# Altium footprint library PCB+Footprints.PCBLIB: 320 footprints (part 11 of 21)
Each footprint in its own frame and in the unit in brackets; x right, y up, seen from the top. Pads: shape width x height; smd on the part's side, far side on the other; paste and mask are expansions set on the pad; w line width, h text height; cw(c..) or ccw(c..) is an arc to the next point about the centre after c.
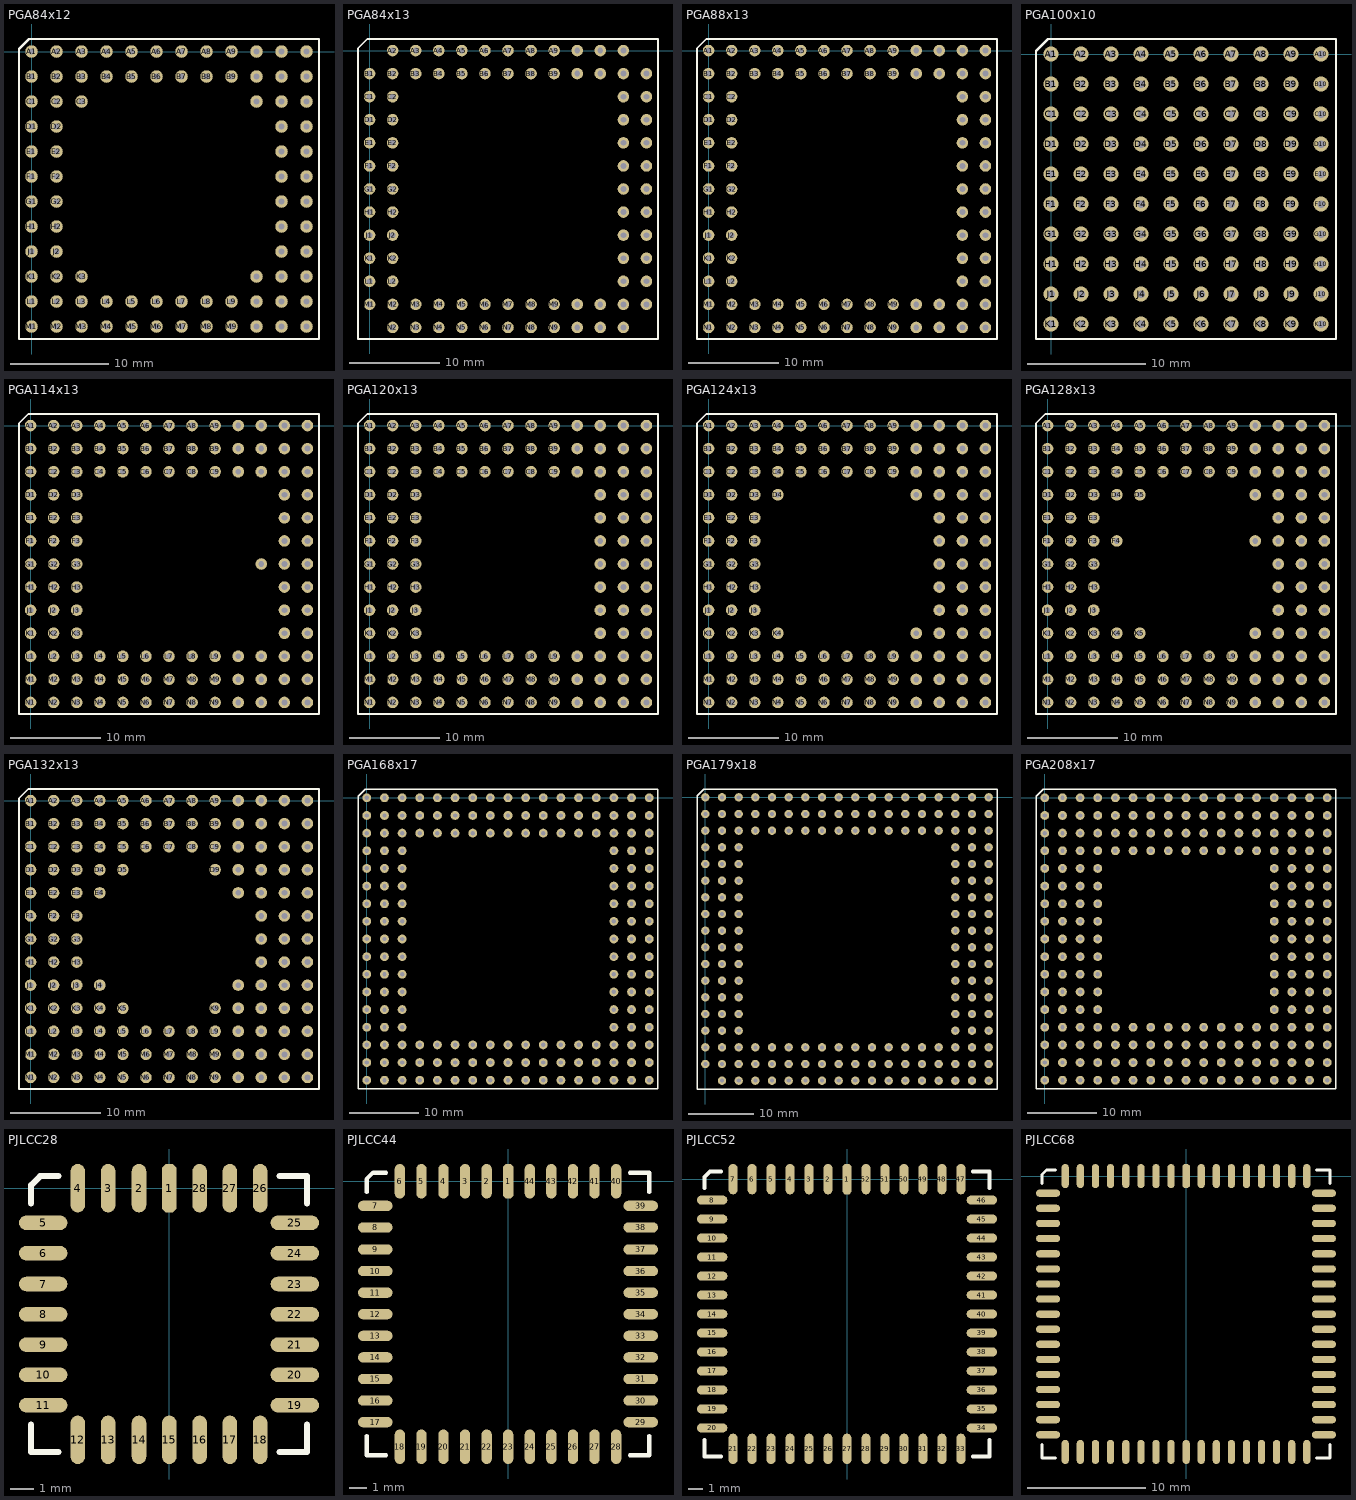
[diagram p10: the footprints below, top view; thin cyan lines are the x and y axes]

## PGA84x12 [mil]
pads (84):
  round 50 hole 25: A1(0,0) A2(100,0) A3(200,0) A4(300,0) A5(400,0) A6(500,0) A7(600,0) A8(700,0) A9(800,0) A10(900,0) A11(1000,0) A12(1100,0) B1(0,-100) B2(100,-100) B3(200,-100) B4(300,-100) B5(400,-100) B6(500,-100) B7(600,-100) B8(700,-100) B9(800,-100) B10(900,-100) B11(1000,-100) B12(1100,-100) C1(0,-200) C2(100,-200) C3(200,-200) C10(900,-200) C11(1000,-200) C12(1100,-200) D1(0,-300) D2(100,-300) D11(1000,-300) D12(1100,-300) E1(0,-400) E2(100,-400) E11(1000,-400) E12(1100,-400) F1(0,-500) F2(100,-500) F11(1000,-500) F12(1100,-500) G1(0,-600) G2(100,-600) G11(1000,-600) G12(1100,-600) H1(0,-700) H2(100,-700) H11(1000,-700) H12(1100,-700) J1(0,-800) J2(100,-800) J11(1000,-800) J12(1100,-800) K1(0,-900) K2(100,-900) K3(200,-900) K10(900,-900) K11(1000,-900) K12(1100,-900) L1(0,-1000) L2(100,-1000) L3(200,-1000) L4(300,-1000) L5(400,-1000) L6(500,-1000) L7(600,-1000) L8(700,-1000) L9(800,-1000) L10(900,-1000) L11(1000,-1000) L12(1100,-1000) M1(0,-1100) M2(100,-1100) M3(200,-1100) M4(300,-1100) M5(400,-1100) M6(500,-1100) M7(600,-1100) M8(700,-1100) M9(800,-1100) M10(900,-1100) M11(1000,-1100) M12(1100,-1100)
TopOverlay:
  lines w8: -50,-1150 1150,-1150 1150,50 -10,50 -50,10 -50,-1150

## PGA84x13 [mil]
pads (84):
  round 50 hole 25: A2(100,0) A3(200,0) A4(300,0) A5(400,0) A6(500,0) A7(600,0) A8(700,0) A9(800,0) A10(900,0) A11(1000,0) A12(1100,0) B1(0,-100) B2(100,-100) B3(200,-100) B4(300,-100) B5(400,-100) B6(500,-100) B7(600,-100) B8(700,-100) B9(800,-100) B10(900,-100) B11(1000,-100) B12(1100,-100) B13(1200,-100) C1(0,-200) C2(100,-200) C12(1100,-200) C13(1200,-200) D1(0,-300) D2(100,-300) D12(1100,-300) D13(1200,-300) E1(0,-400) E2(100,-400) E12(1100,-400) E13(1200,-400) F1(0,-500) F2(100,-500) F12(1100,-500) F13(1200,-500) G1(0,-600) G2(100,-600) G12(1100,-600) G13(1200,-600) H1(0,-700) H2(100,-700) H12(1100,-700) H13(1200,-700) J1(0,-800) J2(100,-800) J12(1100,-800) J13(1200,-800) K1(0,-900) K2(100,-900) K12(1100,-900) K13(1200,-900) L1(0,-1000) L2(100,-1000) L12(1100,-1000) L13(1200,-1000) M1(0,-1100) M2(100,-1100) M3(200,-1100) M4(300,-1100) M5(400,-1100) M6(500,-1100) M7(600,-1100) M8(700,-1100) M9(800,-1100) M10(900,-1100) M11(1000,-1100) M12(1100,-1100) M13(1200,-1100) N2(100,-1200) N3(200,-1200) N4(300,-1200) N5(400,-1200) N6(500,-1200) N7(600,-1200) N8(700,-1200) N9(800,-1200) N10(900,-1200) N11(1000,-1200) N12(1100,-1200)
TopOverlay:
  lines w8: -50,-1250 1250,-1250 1250,50 -10,50 -50,10 -50,-1250

## PGA88x13 [mil]
pads (88):
  round 50 hole 25: A1(0,0) A2(100,0) A3(200,0) A4(300,0) A5(400,0) A6(500,0) A7(600,0) A8(700,0) A9(800,0) A10(900,0) A11(1000,0) A12(1100,0) A13(1200,0) B1(0,-100) B2(100,-100) B3(200,-100) B4(300,-100) B5(400,-100) B6(500,-100) B7(600,-100) B8(700,-100) B9(800,-100) B10(900,-100) B11(1000,-100) B12(1100,-100) B13(1200,-100) C1(0,-200) C2(100,-200) C12(1100,-200) C13(1200,-200) D1(0,-300) D2(100,-300) D12(1100,-300) D13(1200,-300) E1(0,-400) E2(100,-400) E12(1100,-400) E13(1200,-400) F1(0,-500) F2(100,-500) F12(1100,-500) F13(1200,-500) G1(0,-600) G2(100,-600) G12(1100,-600) G13(1200,-600) H1(0,-700) H2(100,-700) H12(1100,-700) H13(1200,-700) J1(0,-800) J2(100,-800) J12(1100,-800) J13(1200,-800) K1(0,-900) K2(100,-900) K12(1100,-900) K13(1200,-900) L1(0,-1000) L2(100,-1000) L12(1100,-1000) L13(1200,-1000) M1(0,-1100) M2(100,-1100) M3(200,-1100) M4(300,-1100) M5(400,-1100) M6(500,-1100) M7(600,-1100) M8(700,-1100) M9(800,-1100) M10(900,-1100) M11(1000,-1100) M12(1100,-1100) M13(1200,-1100) N1(0,-1200) N2(100,-1200) N3(200,-1200) N4(300,-1200) N5(400,-1200) N6(500,-1200) N7(600,-1200) N8(700,-1200) N9(800,-1200) N10(900,-1200) N11(1000,-1200) N12(1100,-1200) N13(1200,-1200)
TopOverlay:
  lines w8: -50,-1250 1250,-1250 1250,50 -10,50 -50,10 -50,-1250

## PGA100x10 [mil]
pads (100):
  round 50 hole 25: A1(0,0) A2(100,0) A3(200,0) A4(300,0) A5(400,0) A6(500,0) A7(600,0) A8(700,0) A9(800,0) A10(900,0) B1(0,-100) B2(100,-100) B3(200,-100) B4(300,-100) B5(400,-100) B6(500,-100) B7(600,-100) B8(700,-100) B9(800,-100) B10(900,-100) C1(0,-200) C2(100,-200) C3(200,-200) C4(300,-200) C5(400,-200) C6(500,-200) C7(600,-200) C8(700,-200) C9(800,-200) C10(900,-200) D1(0,-300) D2(100,-300) D3(200,-300) D4(300,-300) D5(400,-300) D6(500,-300) D7(600,-300) D8(700,-300) D9(800,-300) D10(900,-300) E1(0,-400) E2(100,-400) E3(200,-400) E4(300,-400) E5(400,-400) E6(500,-400) E7(600,-400) E8(700,-400) E9(800,-400) E10(900,-400) F1(0,-500) F2(100,-500) F3(200,-500) F4(300,-500) F5(400,-500) F6(500,-500) F7(600,-500) F8(700,-500) F9(800,-500) F10(900,-500) G1(0,-600) G2(100,-600) G3(200,-600) G4(300,-600) G5(400,-600) G6(500,-600) G7(600,-600) G8(700,-600) G9(800,-600) G10(900,-600) H1(0,-700) H2(100,-700) H3(200,-700) H4(300,-700) H5(400,-700) H6(500,-700) H7(600,-700) H8(700,-700) H9(800,-700) H10(900,-700) J1(0,-800) J2(100,-800) J3(200,-800) J4(300,-800) J5(400,-800) J6(500,-800) J7(600,-800) J8(700,-800) J9(800,-800) J10(900,-800) K1(0,-900) K2(100,-900) K3(200,-900) K4(300,-900) K5(400,-900) K6(500,-900) K7(600,-900) K8(700,-900) K9(800,-900) K10(900,-900)
TopOverlay:
  lines w8: -50,-950 950,-950 950,50 -10,50 -50,10 -50,-950

## PGA114x13 [mil]
pads (114):
  round 50 hole 25: A1(0,0) A2(100,0) A3(200,0) A4(300,0) A5(400,0) A6(500,0) A7(600,0) A8(700,0) A9(800,0) A10(900,0) A11(1000,0) A12(1100,0) A13(1200,0) B1(0,-100) B2(100,-100) B3(200,-100) B4(300,-100) B5(400,-100) B6(500,-100) B7(600,-100) B8(700,-100) B9(800,-100) B10(900,-100) B11(1000,-100) B12(1100,-100) B13(1200,-100) C1(0,-200) C2(100,-200) C3(200,-200) C4(300,-200) C5(400,-200) C6(500,-200) C7(600,-200) C8(700,-200) C9(800,-200) C10(900,-200) C11(1000,-200) C12(1100,-200) C13(1200,-200) D1(0,-300) D2(100,-300) D3(200,-300) D12(1100,-300) D13(1200,-300) E1(0,-400) E2(100,-400) E3(200,-400) E12(1100,-400) E13(1200,-400) F1(0,-500) F2(100,-500) F3(200,-500) F12(1100,-500) F13(1200,-500) G1(0,-600) G2(100,-600) G3(200,-600) G11(1000,-600) G12(1100,-600) G13(1200,-600) H1(0,-700) H2(100,-700) H3(200,-700) H12(1100,-700) H13(1200,-700) J1(0,-800) J2(100,-800) J3(200,-800) J12(1100,-800) J13(1200,-800) K1(0,-900) K2(100,-900) K3(200,-900) K12(1100,-900) K13(1200,-900) L1(0,-1000) L2(100,-1000) L3(200,-1000) L4(300,-1000) L5(400,-1000) L6(500,-1000) L7(600,-1000) L8(700,-1000) L9(800,-1000) L10(900,-1000) L11(1000,-1000) L12(1100,-1000) L13(1200,-1000) M1(0,-1100) M2(100,-1100) M3(200,-1100) M4(300,-1100) M5(400,-1100) M6(500,-1100) M7(600,-1100) M8(700,-1100) M9(800,-1100) M10(900,-1100) M11(1000,-1100) M12(1100,-1100) M13(1200,-1100) N1(0,-1200) N2(100,-1200) N3(200,-1200) N4(300,-1200) N5(400,-1200) N6(500,-1200) N7(600,-1200) N8(700,-1200) N9(800,-1200) N10(900,-1200) N11(1000,-1200) N12(1100,-1200) N13(1200,-1200)
TopOverlay:
  lines w8: -50,-1250 1250,-1250 1250,50 -10,50 -50,10 -50,-1250

## PGA120x13 [mil]
pads (120):
  round 50 hole 25: A1(0,0) A2(100,0) A3(200,0) A4(300,0) A5(400,0) A6(500,0) A7(600,0) A8(700,0) A9(800,0) A10(900,0) A11(1000,0) A12(1100,0) A13(1200,0) B1(0,-100) B2(100,-100) B3(200,-100) B4(300,-100) B5(400,-100) B6(500,-100) B7(600,-100) B8(700,-100) B9(800,-100) B10(900,-100) B11(1000,-100) B12(1100,-100) B13(1200,-100) C1(0,-200) C2(100,-200) C3(200,-200) C4(300,-200) C5(400,-200) C6(500,-200) C7(600,-200) C8(700,-200) C9(800,-200) C10(900,-200) C11(1000,-200) C12(1100,-200) C13(1200,-200) D1(0,-300) D2(100,-300) D3(200,-300) D11(1000,-300) D12(1100,-300) D13(1200,-300) E1(0,-400) E2(100,-400) E3(200,-400) E11(1000,-400) E12(1100,-400) E13(1200,-400) F1(0,-500) F2(100,-500) F3(200,-500) F11(1000,-500) F12(1100,-500) F13(1200,-500) G1(0,-600) G2(100,-600) G3(200,-600) G11(1000,-600) G12(1100,-600) G13(1200,-600) H1(0,-700) H2(100,-700) H3(200,-700) H11(1000,-700) H12(1100,-700) H13(1200,-700) J1(0,-800) J2(100,-800) J3(200,-800) J11(1000,-800) J12(1100,-800) J13(1200,-800) K1(0,-900) K2(100,-900) K3(200,-900) K11(1000,-900) K12(1100,-900) K13(1200,-900) L1(0,-1000) L2(100,-1000) L3(200,-1000) L4(300,-1000) L5(400,-1000) L6(500,-1000) L7(600,-1000) L8(700,-1000) L9(800,-1000) L10(900,-1000) L11(1000,-1000) L12(1100,-1000) L13(1200,-1000) M1(0,-1100) M2(100,-1100) M3(200,-1100) M4(300,-1100) M5(400,-1100) M6(500,-1100) M7(600,-1100) M8(700,-1100) M9(800,-1100) M10(900,-1100) M11(1000,-1100) M12(1100,-1100) M13(1200,-1100) N1(0,-1200) N2(100,-1200) N3(200,-1200) N4(300,-1200) N5(400,-1200) N6(500,-1200) N7(600,-1200) N8(700,-1200) N9(800,-1200) N10(900,-1200) N11(1000,-1200) N12(1100,-1200) N13(1200,-1200)
TopOverlay:
  lines w8: -50,-1250 -50,10 -10,50 1250,50 1250,-1250 -50,-1250

## PGA124x13 [mil]
pads (124):
  round 50 hole 25: A1(0,0) A2(100,0) A3(200,0) A4(300,0) A5(400,0) A6(500,0) A7(600,0) A8(700,0) A9(800,0) A10(900,0) A11(1000,0) A12(1100,0) A13(1200,0) B1(0,-100) B2(100,-100) B3(200,-100) B4(300,-100) B5(400,-100) B6(500,-100) B7(600,-100) B8(700,-100) B9(800,-100) B10(900,-100) B11(1000,-100) B12(1100,-100) B13(1200,-100) C1(0,-200) C2(100,-200) C3(200,-200) C4(300,-200) C5(400,-200) C6(500,-200) C7(600,-200) C8(700,-200) C9(800,-200) C10(900,-200) C11(1000,-200) C12(1100,-200) C13(1200,-200) D1(0,-300) D2(100,-300) D3(200,-300) D4(300,-300) D10(900,-300) D11(1000,-300) D12(1100,-300) D13(1200,-300) E1(0,-400) E2(100,-400) E3(200,-400) E11(1000,-400) E12(1100,-400) E13(1200,-400) F1(0,-500) F2(100,-500) F3(200,-500) F11(1000,-500) F12(1100,-500) F13(1200,-500) G1(0,-600) G2(100,-600) G3(200,-600) G11(1000,-600) G12(1100,-600) G13(1200,-600) H1(0,-700) H2(100,-700) H3(200,-700) H11(1000,-700) H12(1100,-700) H13(1200,-700) J1(0,-800) J2(100,-800) J3(200,-800) J11(1000,-800) J12(1100,-800) J13(1200,-800) K1(0,-900) K2(100,-900) K3(200,-900) K4(300,-900) K10(900,-900) K11(1000,-900) K12(1100,-900) K13(1200,-900) L1(0,-1000) L2(100,-1000) L3(200,-1000) L4(300,-1000) L5(400,-1000) L6(500,-1000) L7(600,-1000) L8(700,-1000) L9(800,-1000) L10(900,-1000) L11(1000,-1000) L12(1100,-1000) L13(1200,-1000) M1(0,-1100) M2(100,-1100) M3(200,-1100) M4(300,-1100) M5(400,-1100) M6(500,-1100) M7(600,-1100) M8(700,-1100) M9(800,-1100) M10(900,-1100) M11(1000,-1100) M12(1100,-1100) M13(1200,-1100) N1(0,-1200) N2(100,-1200) N3(200,-1200) N4(300,-1200) N5(400,-1200) N6(500,-1200) N7(600,-1200) N8(700,-1200) N9(800,-1200) N10(900,-1200) N11(1000,-1200) N12(1100,-1200) N13(1200,-1200)
TopOverlay:
  lines w8: -50,-1250 -50,10 -10,50 1250,50 1250,-1250 -50,-1250

## PGA128x13 [mil]
pads (128):
  round 50 hole 25: A1(0,0) A2(100,0) A3(200,0) A4(300,0) A5(400,0) A6(500,0) A7(600,0) A8(700,0) A9(800,0) A10(900,0) A11(1000,0) A12(1100,0) A13(1200,0) B1(0,-100) B2(100,-100) B3(200,-100) B4(300,-100) B5(400,-100) B6(500,-100) B7(600,-100) B8(700,-100) B9(800,-100) B10(900,-100) B11(1000,-100) B12(1100,-100) B13(1200,-100) C1(0,-200) C2(100,-200) C3(200,-200) C4(300,-200) C5(400,-200) C6(500,-200) C7(600,-200) C8(700,-200) C9(800,-200) C10(900,-200) C11(1000,-200) C12(1100,-200) C13(1200,-200) D1(0,-300) D2(100,-300) D3(200,-300) D4(300,-300) D5(400,-300) D10(900,-300) D11(1000,-300) D12(1100,-300) D13(1200,-300) E1(0,-400) E2(100,-400) E3(200,-400) E11(1000,-400) E12(1100,-400) E13(1200,-400) F1(0,-500) F2(100,-500) F3(200,-500) F4(300,-500) F10(900,-500) F11(1000,-500) F12(1100,-500) F13(1200,-500) G1(0,-600) G2(100,-600) G3(200,-600) G11(1000,-600) G12(1100,-600) G13(1200,-600) H1(0,-700) H2(100,-700) H3(200,-700) H11(1000,-700) H12(1100,-700) H13(1200,-700) J1(0,-800) J2(100,-800) J3(200,-800) J11(1000,-800) J12(1100,-800) J13(1200,-800) K1(0,-900) K2(100,-900) K3(200,-900) K4(300,-900) K5(400,-900) K10(900,-900) K11(1000,-900) K12(1100,-900) K13(1200,-900) L1(0,-1000) L2(100,-1000) L3(200,-1000) L4(300,-1000) L5(400,-1000) L6(500,-1000) L7(600,-1000) L8(700,-1000) L9(800,-1000) L10(900,-1000) L11(1000,-1000) L12(1100,-1000) L13(1200,-1000) M1(0,-1100) M2(100,-1100) M3(200,-1100) M4(300,-1100) M5(400,-1100) M6(500,-1100) M7(600,-1100) M8(700,-1100) M9(800,-1100) M10(900,-1100) M11(1000,-1100) M12(1100,-1100) M13(1200,-1100) N1(0,-1200) N2(100,-1200) N3(200,-1200) N4(300,-1200) N5(400,-1200) N6(500,-1200) N7(600,-1200) N8(700,-1200) N9(800,-1200) N10(900,-1200) N11(1000,-1200) N12(1100,-1200) N13(1200,-1200)
TopOverlay:
  lines w8: -50,-1250 -50,10 -10,50 1250,50 1250,-1250 -50,-1250

## PGA132x13 [mil]
pads (132):
  round 50 hole 25: A1(0,0) A2(100,0) A3(200,0) A4(300,0) A5(400,0) A6(500,0) A7(600,0) A8(700,0) A9(800,0) A10(900,0) A11(1000,0) A12(1100,0) A13(1200,0) B1(0,-100) B2(100,-100) B3(200,-100) B4(300,-100) B5(400,-100) B6(500,-100) B7(600,-100) B8(700,-100) B9(800,-100) B10(900,-100) B11(1000,-100) B12(1100,-100) B13(1200,-100) C1(0,-200) C2(100,-200) C3(200,-200) C4(300,-200) C5(400,-200) C6(500,-200) C7(600,-200) C8(700,-200) C9(800,-200) C10(900,-200) C11(1000,-200) C12(1100,-200) C13(1200,-200) D1(0,-300) D2(100,-300) D3(200,-300) D4(300,-300) D5(400,-300) D9(800,-300) D10(900,-300) D11(1000,-300) D12(1100,-300) D13(1200,-300) E1(0,-400) E2(100,-400) E3(200,-400) E4(300,-400) E10(900,-400) E11(1000,-400) E12(1100,-400) E13(1200,-400) F1(0,-500) F2(100,-500) F3(200,-500) F11(1000,-500) F12(1100,-500) F13(1200,-500) G1(0,-600) G2(100,-600) G3(200,-600) G11(1000,-600) G12(1100,-600) G13(1200,-600) H1(0,-700) H2(100,-700) H3(200,-700) H11(1000,-700) H12(1100,-700) H13(1200,-700) J1(0,-800) J2(100,-800) J3(200,-800) J4(300,-800) J10(900,-800) J11(1000,-800) J12(1100,-800) J13(1200,-800) K1(0,-900) K2(100,-900) K3(200,-900) K4(300,-900) K5(400,-900) K9(800,-900) K10(900,-900) K11(1000,-900) K12(1100,-900) K13(1200,-900) L1(0,-1000) L2(100,-1000) L3(200,-1000) L4(300,-1000) L5(400,-1000) L6(500,-1000) L7(600,-1000) L8(700,-1000) L9(800,-1000) L10(900,-1000) L11(1000,-1000) L12(1100,-1000) L13(1200,-1000) M1(0,-1100) M2(100,-1100) M3(200,-1100) M4(300,-1100) M5(400,-1100) M6(500,-1100) M7(600,-1100) M8(700,-1100) M9(800,-1100) M10(900,-1100) M11(1000,-1100) M12(1100,-1100) M13(1200,-1100) N1(0,-1200) N2(100,-1200) N3(200,-1200) N4(300,-1200) N5(400,-1200) N6(500,-1200) N7(600,-1200) N8(700,-1200) N9(800,-1200) N10(900,-1200) N11(1000,-1200) N12(1100,-1200) N13(1200,-1200)
TopOverlay:
  lines w8: -50,-1250 -50,10 -10,50 1250,50 1250,-1250 -50,-1250

## PGA168x17 [mil]
pads (168):
  round 50 hole 25: A1(0,0) A2(100,0) A3(200,0) A4(300,0) A5(400,0) A6(500,0) A7(600,0) A8(700,0) A9(800,0) A10(900,0) A11(1000,0) A12(1100,0) A13(1200,0) A14(1300,0) A15(1400,0) A16(1500,0) A17(1600,0) B1(0,-100) B2(100,-100) B3(200,-100) B4(300,-100) B5(400,-100) B6(500,-100) B7(600,-100) B8(700,-100) B9(800,-100) B10(900,-100) B11(1000,-100) B12(1100,-100) B13(1200,-100) B14(1300,-100) B15(1400,-100) B16(1500,-100) B17(1600,-100) C1(0,-200) C2(100,-200) C3(200,-200) C4(300,-200) C5(400,-200) C6(500,-200) C7(600,-200) C8(700,-200) C9(800,-200) C10(900,-200) C11(1000,-200) C12(1100,-200) C13(1200,-200) C14(1300,-200) C15(1400,-200) C16(1500,-200) C17(1600,-200) D1(0,-300) D2(100,-300) D3(200,-300) D15(1400,-300) D16(1500,-300) D17(1600,-300) E1(0,-400) E2(100,-400) E3(200,-400) E15(1400,-400) E16(1500,-400) E17(1600,-400) F1(0,-500) F2(100,-500) F3(200,-500) F15(1400,-500) F16(1500,-500) F17(1600,-500) G1(0,-600) G2(100,-600) G3(200,-600) G15(1400,-600) G16(1500,-600) G17(1600,-600) H1(0,-700) H2(100,-700) H3(200,-700) H15(1400,-700) H16(1500,-700) H17(1600,-700) J1(0,-800) J2(100,-800) J3(200,-800) J15(1400,-800) J16(1500,-800) J17(1600,-800) K1(0,-900) K2(100,-900) K3(200,-900) K15(1400,-900) K16(1500,-900) K17(1600,-900) L1(0,-1000) L2(100,-1000) L3(200,-1000) L15(1400,-1000) L16(1500,-1000) L17(1600,-1000) M1(0,-1100) M2(100,-1100) M3(200,-1100) M15(1400,-1100) M16(1500,-1100) M17(1600,-1100) N1(0,-1200) N2(100,-1200) N3(200,-1200) N15(1400,-1200) N16(1500,-1200) N17(1600,-1200) P1(0,-1300) P2(100,-1300) P3(200,-1300) P15(1400,-1300) P16(1500,-1300) P17(1600,-1300) Q1(0,-1400) Q2(100,-1400) Q3(200,-1400) Q4(300,-1400) Q5(400,-1400) Q6(500,-1400) Q7(600,-1400) Q8(700,-1400) Q9(800,-1400) Q10(900,-1400) Q11(1000,-1400) Q12(1100,-1400) Q13(1200,-1400) Q14(1300,-1400) Q15(1400,-1400) Q16(1500,-1400) Q17(1600,-1400) R1(0,-1500) R2(100,-1500) R3(200,-1500) R4(300,-1500) R5(400,-1500) R6(500,-1500) R7(600,-1500) R8(700,-1500) R9(800,-1500) R10(900,-1500) R11(1000,-1500) R12(1100,-1500) R13(1200,-1500) R14(1300,-1500) R15(1400,-1500) R16(1500,-1500) R17(1600,-1500) S1(0,-1600) S2(100,-1600) S3(200,-1600) S4(300,-1600) S5(400,-1600) S6(500,-1600) S7(600,-1600) S8(700,-1600) S9(800,-1600) S10(900,-1600) S11(1000,-1600) S12(1100,-1600) S13(1200,-1600) S14(1300,-1600) S15(1400,-1600) S16(1500,-1600) S17(1600,-1600)
TopOverlay:
  lines w8: -50,-1650 -50,10 -10,50 1650,50 1650,-1650 -50,-1650

## PGA179x18 [mil]
pads (179):
  round 50 hole 25: A1(0,0) A2(100,0) A3(200,0) A4(300,0) A5(400,0) A6(500,0) A7(600,0) A8(700,0) A9(800,0) A10(900,0) A11(1000,0) A12(1100,0) A13(1200,0) A14(1300,0) A15(1400,0) A16(1500,0) A17(1600,0) A18(1700,0) B1(0,-100) B2(100,-100) B3(200,-100) B4(300,-100) B5(400,-100) B6(500,-100) B7(600,-100) B8(700,-100) B9(800,-100) B10(900,-100) B11(1000,-100) B12(1100,-100) B13(1200,-100) B14(1300,-100) B15(1400,-100) B16(1500,-100) B17(1600,-100) B18(1700,-100) C1(0,-200) C2(100,-200) C3(200,-200) C4(300,-200) C5(400,-200) C6(500,-200) C7(600,-200) C8(700,-200) C9(800,-200) C10(900,-200) C11(1000,-200) C12(1100,-200) C13(1200,-200) C14(1300,-200) C15(1400,-200) C16(1500,-200) C17(1600,-200) C18(1700,-200) D1(0,-300) D2(100,-300) D3(200,-300) D16(1500,-300) D17(1600,-300) D18(1700,-300) E1(0,-400) E2(100,-400) E3(200,-400) E16(1500,-400) E17(1600,-400) E18(1700,-400) F1(0,-500) F2(100,-500) F3(200,-500) F16(1500,-500) F17(1600,-500) F18(1700,-500) G1(0,-600) G2(100,-600) G3(200,-600) G16(1500,-600) G17(1600,-600) G18(1700,-600) H1(0,-700) H2(100,-700) H3(200,-700) H16(1500,-700) H17(1600,-700) H18(1700,-700) J1(0,-800) J2(100,-800) J3(200,-800) J16(1500,-800) J17(1600,-800) J18(1700,-800) K1(0,-900) K2(100,-900) K3(200,-900) K16(1500,-900) K17(1600,-900) K18(1700,-900) L1(0,-1000) L2(100,-1000) L3(200,-1000) L16(1500,-1000) L17(1600,-1000) L18(1700,-1000) M1(0,-1100) M2(100,-1100) M3(200,-1100) M16(1500,-1100) M17(1600,-1100) M18(1700,-1100) N1(0,-1200) N2(100,-1200) N3(200,-1200) N16(1500,-1200) N17(1600,-1200) N18(1700,-1200) P1(0,-1300) P2(100,-1300) P3(200,-1300) P16(1500,-1300) P17(1600,-1300) P18(1700,-1300) Q1(0,-1400) Q2(100,-1400) Q3(200,-1400) Q16(1500,-1400) Q17(1600,-1400) Q18(1700,-1400) R1(0,-1500) R2(100,-1500) R3(200,-1500) R4(300,-1500) R5(400,-1500) R6(500,-1500) R7(600,-1500) R8(700,-1500) R9(800,-1500) R10(900,-1500) R11(1000,-1500) R12(1100,-1500) R13(1200,-1500) R14(1300,-1500) R15(1400,-1500) R16(1500,-1500) R17(1600,-1500) R18(1700,-1500) S1(0,-1600) S2(100,-1600) S3(200,-1600) S4(300,-1600) S5(400,-1600) S6(500,-1600) S7(600,-1600) S8(700,-1600) S9(800,-1600) S10(900,-1600) S11(1000,-1600) S12(1100,-1600) S13(1200,-1600) S14(1300,-1600) S15(1400,-1600) S16(1500,-1600) S17(1600,-1600) S18(1700,-1600) T2(100,-1700) T3(200,-1700) T4(300,-1700) T5(400,-1700) T6(500,-1700) T7(600,-1700) T8(700,-1700) T9(800,-1700) T10(900,-1700) T11(1000,-1700) T12(1100,-1700) T13(1200,-1700) T14(1300,-1700) T15(1400,-1700) T16(1500,-1700) T17(1600,-1700) T18(1700,-1700)
TopOverlay:
  lines w8: -50,-1750 -50,10 -10,50 1750,50 1750,-1750 -50,-1750

## PGA208x17 [mil]
pads (208):
  round 50 hole 25: A1(0,0) A2(100,0) A3(200,0) A4(300,0) A5(400,0) A6(500,0) A7(600,0) A8(700,0) A9(800,0) A10(900,0) A11(1000,0) A12(1100,0) A13(1200,0) A14(1300,0) A15(1400,0) A16(1500,0) A17(1600,0) B1(0,-100) B2(100,-100) B3(200,-100) B4(300,-100) B5(400,-100) B6(500,-100) B7(600,-100) B8(700,-100) B9(800,-100) B10(900,-100) B11(1000,-100) B12(1100,-100) B13(1200,-100) B14(1300,-100) B15(1400,-100) B16(1500,-100) B17(1600,-100) C1(0,-200) C2(100,-200) C3(200,-200) C4(300,-200) C5(400,-200) C6(500,-200) C7(600,-200) C8(700,-200) C9(800,-200) C10(900,-200) C11(1000,-200) C12(1100,-200) C13(1200,-200) C14(1300,-200) C15(1400,-200) C16(1500,-200) C17(1600,-200) D1(0,-300) D2(100,-300) D3(200,-300) D4(300,-300) D5(400,-300) D6(500,-300) D7(600,-300) D8(700,-300) D9(800,-300) D10(900,-300) D11(1000,-300) D12(1100,-300) D13(1200,-300) D14(1300,-300) D15(1400,-300) D16(1500,-300) D17(1600,-300) E1(0,-400) E2(100,-400) E3(200,-400) E4(300,-400) E14(1300,-400) E15(1400,-400) E16(1500,-400) E17(1600,-400) F1(0,-500) F2(100,-500) F3(200,-500) F4(300,-500) F14(1300,-500) F15(1400,-500) F16(1500,-500) F17(1600,-500) G1(0,-600) G2(100,-600) G3(200,-600) G4(300,-600) G14(1300,-600) G15(1400,-600) G16(1500,-600) G17(1600,-600) H1(0,-700) H2(100,-700) H3(200,-700) H4(300,-700) H14(1300,-700) H15(1400,-700) H16(1500,-700) H17(1600,-700) J1(0,-800) J2(100,-800) J3(200,-800) J4(300,-800) J14(1300,-800) J15(1400,-800) J16(1500,-800) J17(1600,-800) K1(0,-900) K2(100,-900) K3(200,-900) K4(300,-900) K14(1300,-900) K15(1400,-900) K16(1500,-900) K17(1600,-900) L1(0,-1000) L2(100,-1000) L3(200,-1000) L4(300,-1000) L14(1300,-1000) L15(1400,-1000) L16(1500,-1000) L17(1600,-1000) M1(0,-1100) M2(100,-1100) M3(200,-1100) M4(300,-1100) M14(1300,-1100) M15(1400,-1100) M16(1500,-1100) M17(1600,-1100) N1(0,-1200) N2(100,-1200) N3(200,-1200) N4(300,-1200) N14(1300,-1200) N15(1400,-1200) N16(1500,-1200) N17(1600,-1200) P1(0,-1300) P2(100,-1300) P3(200,-1300) P4(300,-1300) P5(400,-1300) P6(500,-1300) P7(600,-1300) P8(700,-1300) P9(800,-1300) P10(900,-1300) P11(1000,-1300) P12(1100,-1300) P13(1200,-1300) P14(1300,-1300) P15(1400,-1300) P16(1500,-1300) P17(1600,-1300) Q1(0,-1400) Q2(100,-1400) Q3(200,-1400) Q4(300,-1400) Q5(400,-1400) Q6(500,-1400) Q7(600,-1400) Q8(700,-1400) Q9(800,-1400) Q10(900,-1400) Q11(1000,-1400) Q12(1100,-1400) Q13(1200,-1400) Q14(1300,-1400) Q15(1400,-1400) Q16(1500,-1400) Q17(1600,-1400) R1(0,-1500) R2(100,-1500) R3(200,-1500) R4(300,-1500) R5(400,-1500) R6(500,-1500) R7(600,-1500) R8(700,-1500) R9(800,-1500) R10(900,-1500) R11(1000,-1500) R12(1100,-1500) R13(1200,-1500) R14(1300,-1500) R15(1400,-1500) R16(1500,-1500) R17(1600,-1500) S1(0,-1600) S2(100,-1600) S3(200,-1600) S4(300,-1600) S5(400,-1600) S6(500,-1600) S7(600,-1600) S8(700,-1600) S9(800,-1600) S10(900,-1600) S11(1000,-1600) S12(1100,-1600) S13(1200,-1600) S14(1300,-1600) S15(1400,-1600) S16(1500,-1600) S17(1600,-1600)
TopOverlay:
  lines w8: -50,-1650 -50,10 -10,50 1650,50 1650,-1650 -50,-1650

## PJLCC28 [mil]
pads (28):
  oct 24x80 smd: 1(0,0)
  oval 24x80 smd: 2(-50,0) 3(-101,0) 4(-151,0) 12(-151,-415) 13(-101,-415) 14(-50,-415) 15(0,-415) 16(50,-415) 17(100,-415) 18(150,-415) 26(150,0) 27(100,0) 28(50,0)
  oval 80x24 smd: 5(-208,-57) 6(-208,-107) 7(-208,-158) 8(-208,-208) 9(-208,-258) 10(-208,-308) 11(-208,-358) 19(207,-358) 20(207,-308) 21(207,-258) 22(207,-208) 23(207,-158) 24(207,-107) 25(207,-57)
TopOverlay:
  lines w10: -228,-390 -228,-435 -183,-435 ; -228,-25 -228,5 -213,20 -183,20 ; 182,-435 227,-435 227,-390 ; 182,20 227,20 227,-25

## PJLCC44 [mil]
pads (44):
  oct 24x80 smd: 1(0,0)
  oval 24x80 smd: 2(-50,0) 3(-100,0) 4(-150,0) 5(-201,0) 6(-251,0) 18(-251,-615) 19(-201,-615) 20(-150,-615) 21(-100,-615) 22(-50,-615) 23(0,-615) 24(50,-615) 25(100,-615) 26(150,-615) 27(200,-615) 28(250,-615) 40(250,0) 41(200,0) 42(150,0) 43(100,0) 44(50,0)
  oval 80x24 smd: 7(-308,-57) 8(-308,-107) 9(-308,-158) 10(-308,-208) 11(-308,-258) 12(-308,-308) 13(-308,-358) 14(-308,-408) 15(-308,-458) 16(-308,-508) 17(-308,-558) 29(307,-558) 30(307,-508) 31(307,-458) 32(307,-408) 33(307,-358) 34(307,-308) 35(307,-258) 36(307,-208) 37(307,-158) 38(307,-107) 39(307,-57)
TopOverlay:
  lines w10: -328,-590 -328,-635 -283,-635 ; -328,-25 -328,5 -313,20 -283,20 ; 282,-635 327,-635 327,-590 ; 282,20 327,20 327,-25

## PJLCC52 [mil]
pads (52):
  oct 24x80 smd: 1(0,0)
  oval 24x80 smd: 2(-50,0) 3(-100,0) 4(-150,0) 5(-200,0) 6(-250,0) 7(-300,0) 21(-300,-710) 22(-250,-710) 23(-200,-710) 24(-150,-710) 25(-100,-710) 26(-50,-710) 27(0,-710) 28(50,-710) 29(100,-710) 30(150,-710) 31(200,-710) 32(250,-710) 33(300,-710) 47(300,0) 48(250,0) 49(200,0) 50(150,0) 51(100,0) 52(50,0)
  oval 80x24 smd: 8(-355,-55) 9(-355,-105) 10(-355,-155) 11(-355,-205) 12(-355,-255) 13(-355,-305) 14(-355,-355) 15(-355,-405) 16(-355,-455) 17(-355,-505) 18(-355,-555) 19(-355,-605) 20(-355,-655) 34(355,-655) 35(355,-605) 36(355,-555) 37(355,-505) 38(355,-455) 39(355,-405) 40(355,-355) 41(355,-305) 42(355,-255) 43(355,-205) 44(355,-155) 45(355,-105) 46(355,-55)
TopOverlay:
  lines w10: -375,-687 -375,-730 -332,-730 ; -375,-23 -375,6 -361,20 -332,20 ; 332,-730 375,-730 375,-687 ; 332,20 375,20 375,-23

## PJLCC68 [mil]
pads (68):
  oct 24x80 smd: 1(0,0)
  oval 24x80 smd: 2(-50,0) 3(-100,0) 4(-150,0) 5(-200,0) 6(-251,0) 7(-301,0) 8(-351,0) 9(-401,0) 27(-401,-915) 28(-351,-915) 29(-301,-915) 30(-251,-915) 31(-200,-915) 32(-150,-915) 33(-100,-915) 34(-50,-915) 35(0,-915) 36(50,-915) 37(100,-915) 38(150,-915) 39(200,-915) 40(250,-915) 41(300,-915) 42(350,-915) 43(400,-915) 61(400,0) 62(350,0) 63(300,0) 64(250,0) 65(200,0) 66(150,0) 67(100,0) 68(50,0)
  oval 80x24 smd: 10(-458,-57) 11(-458,-107) 12(-458,-157) 13(-458,-207) 14(-458,-258) 15(-458,-308) 16(-458,-358) 17(-458,-408) 18(-458,-458) 19(-458,-508) 20(-458,-558) 21(-458,-608) 22(-458,-658) 23(-458,-708) 24(-458,-758) 25(-458,-808) 26(-458,-858) 44(457,-858) 45(457,-808) 46(457,-758) 47(457,-708) 48(457,-658) 49(457,-608) 50(457,-558) 51(457,-508) 52(457,-458) 53(457,-408) 54(457,-358) 55(457,-308) 56(457,-258) 57(457,-207) 58(457,-157) 59(457,-107) 60(457,-57)
TopOverlay:
  lines w10: -478,-890 -478,-935 -433,-935 ; -478,-25 -478,5 -463,20 -433,20 ; 432,-935 477,-935 477,-890 ; 432,20 477,20 477,-25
